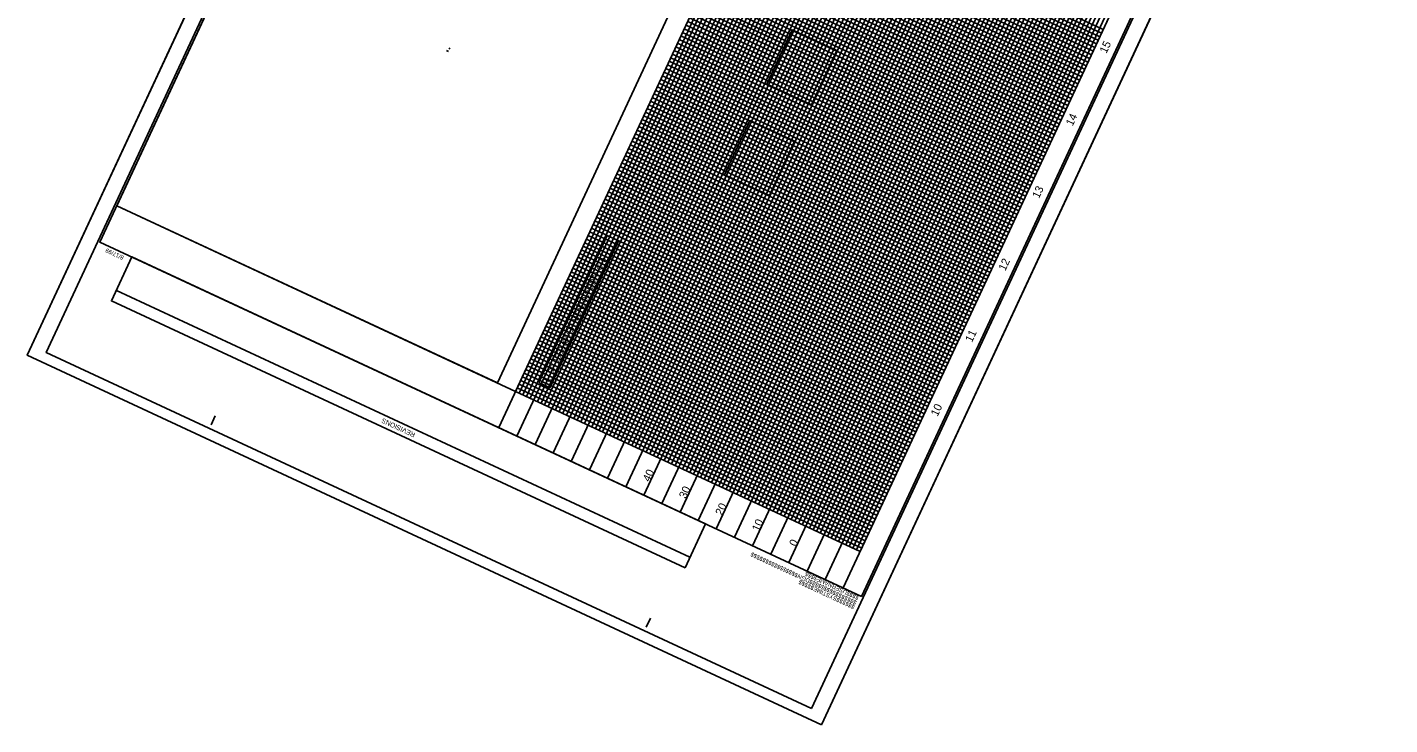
# Model space of a CAD drawing. Extents: x 2532214 to 2533961, y 714631 to 717266.
# Drawn here: x 2532214 to 2533917, y 714631 to 715503 of the extents above; entities that cross this region are included whole.
import ezdxf

# ---------------------------------------------------------------- set-up
doc = ezdxf.new("R2010")
doc.units = 0
for name, color, linetype in [('Default', 7, 'Continuous'), ('Exist Vertical Profile Horizontal Axis Label Major', 7, 'Continuous'), ('Exist Vertical Profile Vertical Axis Label', 7, 'Continuous'), ('Prop VPI Label', 7, 'Continuous'), ('Raster_Level_0', 7, 'Continuous'), ('Scratch_Level_0', 7, 'Continuous'), ('Scratch_Level_3', 7, 'Continuous'), ('Sheet Block Revision CELL', 7, 'Continuous'), ('Sheet Block System Information CELL', 7, 'Continuous'), ('Sheet Cutting Line CELL', 7, 'Continuous'), ('Sheet DOT Grid CELL', 7, 'Continuous'), ('Sheet Layout Plan Border', 7, 'Continuous'), ('Sheet Plan And Profile CELL', 7, 'Continuous'), ('Sheet Plot Border Inside CELL', 7, 'Continuous'), ('Sheet Plot Border Outside CELL', 7, 'Continuous'), ('Sheet Profile Grid Major CELL', 7, 'Continuous'), ('Sheet Profile Grid Middle CELL', 7, 'Continuous'), ('Sheet Profile Grid Minor CELL', 7, 'Continuous')]:
    doc.layers.add(name, color=color, linetype=linetype)

msp = doc.modelspace()

# ---------------------------------------------------------------- linework, layer by layer
at = {"layer": 'Default'}
for points in [[(2533138.5, 715432.1), (2533170.1, 715500.1), (2533226.1, 715474), (2533194.4, 715406)], [(2533138.5, 715432.1), (2533170.1, 715500.1), (2533226.1, 715474), (2533194.4, 715406)], [(2533085.7, 715318.7), (2533117.4, 715386.7), (2533173.3, 715360.7), (2533141.7, 715292.7)], [(2533085.7, 715318.7), (2533117.4, 715386.7), (2533173.3, 715360.7), (2533141.7, 715292.7)], [(2532853.4, 715059), (2532939, 715242.9), (2532953.1, 715236.4), (2532867.5, 715052.5)], [(2532853.4, 715059), (2532939, 715242.9), (2532953.1, 715236.4), (2532867.5, 715052.5)]]:
    msp.add_lwpolyline(points, close=True, dxfattribs=at)
at = {"layer": 'Raster_Level_0'}
for p, q in [((2532738.3, 715474.1), (2532740.7, 715473)), ((2532741, 715477.2), (2532742.8, 715476.4))]:
    msp.add_line(p, q, dxfattribs=at)
at = {"layer": 'Scratch_Level_0'}
msp.add_lwpolyline([(2532325.9, 715280), (2532853.1, 716413.3), (2533042.4, 716325.3), (2533126.8, 716506.7), (2533345.5, 716404.9), (2533436.2, 716362.7), (2533229.5, 715918.4), (2532824.5, 715048)], close=True, dxfattribs=at)
at = {"layer": 'Scratch_Level_3'}
msp.add_lwpolyline([(2532824.5, 715048), (2533229.5, 715918.4), (2533415.1, 716317.4), (2533539.1, 716259.7), (2533845.8, 716117), (2533255.2, 714847.7)], close=True, dxfattribs=at)
at = {"layer": 'Sheet Block Revision CELL'}
msp.add_line((2533042.4, 714840.8), (2532325.6, 715174.3), dxfattribs=at)
msp.add_lwpolyline([(2533036.3, 714827.6), (2532319.4, 715161.1), (2532345, 715216), (2533061.8, 714882.5)], close=True, dxfattribs=at)
at = {"layer": 'Sheet Block System Information CELL'}
msp.add_line((2533256.8, 714791.8), (2533256.8, 714791.8), dxfattribs=at)
at = {"layer": 'Sheet Cutting Line CELL'}
for p, q in [((2532924.3, 716619.6), (2532214.1, 715093.2)), ((2533206.9, 714631.3), (2533917.1, 716157.7)), ((2532214.1, 715093.2), (2533206.9, 714631.3))]:
    msp.add_line(p, q, dxfattribs=at)
at = {"layer": 'Sheet DOT Grid CELL'}
for p, q in [((2532939.4, 714939.4), (2533572.2, 716299.4)), ((2532848.8, 714981.6), (2533460.4, 716296.3)), ((2532894.1, 714960.5), (2533505.8, 716275.2)), ((2532984.8, 714918.3), (2533617.5, 716278.3)), ((2533030.1, 714897.2), (2533662.9, 716257.2)), ((2533075.4, 714876.1), (2533708.2, 716236.2)), ((2533120.8, 714855), (2533753.5, 716215.1)), ((2533166.1, 714834), (2533798.9, 716194)), ((2533211.4, 714812.9), (2533844.2, 716172.9)), ((2533119.8, 715682.7), (2533550.5, 715482.3)), ((2533098.7, 715637.4), (2533529.4, 715437)), ((2533077.6, 715592), (2533508.3, 715391.7)), ((2533056.5, 715546.7), (2533487.2, 715346.3)), ((2533035.4, 715501.4), (2533466.1, 715301)), ((2533014.4, 715456), (2533445, 715255.7)), ((2532993.3, 715410.7), (2533423.9, 715210.3)), ((2532972.2, 715365.4), (2533402.8, 715165)), ((2532951.1, 715320), (2533381.8, 715119.7)), ((2532930, 715274.7), (2533360.7, 715074.3)), ((2532908.9, 715229.4), (2533339.6, 715029)), ((2532887.8, 715184), (2533318.5, 714983.7)), ((2532866.7, 715138.7), (2533297.4, 714938.3)), ((2532845.6, 715093.4), (2533276.3, 714893))]:
    msp.add_line(p, q, dxfattribs=at)
at = {"layer": 'Sheet Layout Plan Border'}
msp.add_lwpolyline([(2532801.9, 715058.6), (2532325.9, 715280), (2532853.1, 716413.3), (2533042.4, 716325.3), (2533105.7, 716461.3), (2533392.4, 716327.9)], close=True, dxfattribs=at)
at = {"layer": 'Sheet Plan And Profile CELL'}
for p, q in [((2533436.2, 716362.7), (2532803.4, 715002.7)), ((2533866.9, 716162.3), (2533234.1, 714802.3)), ((2532443.9, 715006.2), (2532449.1, 715017.5)), ((2533256.8, 714791.8), (2533256.8, 714791.8)), ((2533256.8, 714791.8), (2533256.8, 714791.8)), ((2533256.8, 714791.8), (2533256.8, 714791.8)), ((2533256.8, 714791.8), (2533256.8, 714791.8)), ((2533256.8, 714791.8), (2533256.8, 714791.8)), ((2532987.9, 714753.1), (2532993.1, 714764.4))]:
    msp.add_line(p, q, dxfattribs=at)
msp.add_lwpolyline([(2532937.5, 716594.7), (2532304.8, 715234.7), (2533256.8, 714791.8), (2533889.5, 716151.8)], close=True, dxfattribs=at)
at = {"layer": 'Sheet Plot Border Inside CELL'}
msp.add_lwpolyline([(2533194.3, 714651.5), (2533897.1, 716162.1), (2532940.5, 716607.1), (2532237.8, 715096.6)], close=True, dxfattribs=at)
at = {"layer": 'Sheet Plot Border Outside CELL'}
msp.add_lwpolyline([(2533206.9, 714631.3), (2533917.1, 716157.7), (2532924.3, 716619.6), (2532214.1, 715093.2)], close=True, dxfattribs=at)
at = {"layer": 'Sheet Profile Grid Major CELL'}
for p, q in [((2533481.5, 716341.6), (2532848.8, 714981.6)), ((2532894.1, 714960.5), (2533526.9, 716320.5)), ((2533572.2, 716299.4), (2532939.4, 714939.4)), ((2532984.8, 714918.3), (2533617.5, 716278.3)), ((2533662.9, 716257.2), (2533030.1, 714897.2)), ((2533075.4, 714876.1), (2533708.2, 716236.2)), ((2533753.5, 716215.1), (2533120.8, 714855)), ((2533166.1, 714834), (2533798.9, 716194)), ((2533844.2, 716172.9), (2533211.4, 714812.9)), ((2533550.5, 715482.3), (2533119.8, 715682.7)), ((2533098.7, 715637.4), (2533529.4, 715437)), ((2533508.3, 715391.7), (2533077.6, 715592)), ((2533056.5, 715546.7), (2533487.2, 715346.3)), ((2533466.1, 715301), (2533035.4, 715501.4)), ((2533014.4, 715456), (2533445, 715255.7)), ((2533423.9, 715210.3), (2532993.3, 715410.7)), ((2532972.2, 715365.4), (2533402.8, 715165)), ((2533381.8, 715119.7), (2532951.1, 715320)), ((2532930, 715274.7), (2533360.7, 715074.3)), ((2533339.6, 715029), (2532908.9, 715229.4)), ((2532887.8, 715184), (2533318.5, 714983.7)), ((2533297.4, 714938.3), (2532866.7, 715138.7)), ((2532845.6, 715093.4), (2533276.3, 714893)), ((2533255.2, 714847.7), (2532824.5, 715048))]:
    msp.add_line(p, q, dxfattribs=at)
at = {"layer": 'Sheet Profile Grid Middle CELL'}
for p, q in [((2532826.1, 714992.1), (2533458.9, 716352.2)), ((2533504.2, 716331.1), (2532871.4, 714971.1)), ((2532916.8, 714950), (2533549.5, 716310)), ((2533594.9, 716288.9), (2532962.1, 714928.9)), ((2533007.4, 714907.8), (2533640.2, 716267.8)), ((2533685.5, 716246.7), (2533052.8, 714886.7)), ((2533098.1, 714865.6), (2533730.9, 716225.6)), ((2533776.2, 716204.5), (2533143.4, 714844.5)), ((2533188.8, 714823.4), (2533821.5, 716183.4)), ((2533109.3, 715660), (2533539.9, 715459.7)), ((2533518.8, 715414.3), (2533088.2, 715614.7)), ((2533067.1, 715569.4), (2533497.8, 715369)), ((2533476.7, 715323.7), (2533046, 715524)), ((2533024.9, 715478.7), (2533455.6, 715278.3)), ((2533434.5, 715233), (2533003.8, 715433.4)), ((2532982.7, 715388), (2533413.4, 715187.7)), ((2533392.3, 715142.3), (2532961.6, 715342.7)), ((2532940.5, 715297.4), (2533371.2, 715097)), ((2533350.1, 715051.7), (2532919.4, 715252)), ((2532898.4, 715206.7), (2533329, 715006.3)), ((2533307.9, 714961), (2532877.3, 715161.4)), ((2532856.2, 715116), (2533286.8, 714915.7)), ((2533265.8, 714870.3), (2532835.1, 715070.7))]:
    msp.add_line(p, q, dxfattribs=at)
at = {"layer": 'Sheet Profile Grid Minor CELL'}
for p, q in [((2533419.6, 716315.3), (2532829.1, 715045.9)), ((2532833.6, 715043.8), (2533424.2, 716313.2)), ((2533428.7, 716311), (2532838.1, 715041.7)), ((2532842.7, 715039.6), (2533433.2, 716308.9)), ((2533442.3, 716304.7), (2532851.7, 715035.4)), ((2532856.3, 715033.3), (2533446.8, 716302.6)), ((2533451.4, 716300.5), (2532860.8, 715031.1)), ((2532865.3, 715029), (2533455.9, 716298.4)), ((2533465, 716294.2), (2532874.4, 715024.8)), ((2532878.9, 715022.7), (2533469.5, 716292.1)), ((2533474, 716289.9), (2532883.5, 715020.6)), ((2532888, 715018.5), (2533478.6, 716287.8)), ((2533487.6, 716283.6), (2532897.1, 715014.3)), ((2532901.6, 715012.2), (2533492.2, 716281.5)), ((2533496.7, 716279.4), (2532906.1, 715010.1)), ((2532910.7, 715007.9), (2533501.2, 716277.3)), ((2532919.7, 715003.7), (2533510.3, 716273.1)), ((2533514.8, 716271), (2532924.3, 715001.6)), ((2532928.8, 714999.5), (2533519.4, 716268.9)), ((2533523.9, 716266.7), (2532933.3, 714997.4)), ((2532942.4, 714993.2), (2533533, 716262.5)), ((2533537.5, 716260.4), (2532946.9, 714991.1)), ((2532951.5, 714989), (2533542, 716258.3)), ((2533546.6, 716256.2), (2532956, 714986.9)), ((2532965.1, 714982.6), (2533555.6, 716252)), ((2533560.2, 716249.9), (2532969.6, 714980.5)), ((2532974.1, 714978.4), (2533564.7, 716247.8)), ((2533569.2, 716245.7), (2532978.7, 714976.3)), ((2532987.7, 714972.1), (2533578.3, 716241.4)), ((2533582.8, 716239.3), (2532992.3, 714970)), ((2532996.8, 714967.9), (2533587.4, 716237.2)), ((2533591.9, 716235.1), (2533001.3, 714965.8)), ((2533010.4, 714961.5), (2533601, 716230.9)), ((2533605.5, 716228.8), (2533014.9, 714959.4)), ((2533019.5, 714957.3), (2533610, 716226.7)), ((2533614.6, 716224.6), (2533024, 714955.2)), ((2533033.1, 714951), (2533623.6, 716220.3)), ((2533628.2, 716218.2), (2533037.6, 714948.9)), ((2533042.1, 714946.8), (2533632.7, 716216.1)), ((2533637.2, 716214), (2533046.7, 714944.7)), ((2533055.7, 714940.5), (2533646.3, 716209.8)), ((2533650.8, 716207.7), (2533060.3, 714938.3)), ((2533064.8, 714936.2), (2533655.4, 716205.6)), ((2533659.9, 716203.5), (2533069.3, 714934.1)), ((2533078.4, 714929.9), (2533669, 716199.3)), ((2533673.5, 716197.1), (2533082.9, 714927.8)), ((2533087.5, 714925.7), (2533678, 716195)), ((2533682.6, 716192.9), (2533092, 714923.6)), ((2533101.1, 714919.4), (2533691.6, 716188.7)), ((2533696.2, 716186.6), (2533105.6, 714917.3)), ((2533110.1, 714915.1), (2533700.7, 716184.5)), ((2533705.2, 716182.4), (2533114.7, 714913)), ((2533123.7, 714908.8), (2533714.3, 716178.2)), ((2533718.8, 716176.1), (2533128.3, 714906.7)), ((2533132.8, 714904.6), (2533723.4, 716173.9)), ((2533727.9, 716171.8), (2533137.3, 714902.5)), ((2533146.4, 714898.3), (2533737, 716167.6)), ((2533741.5, 716165.5), (2533150.9, 714896.2)), ((2533155.5, 714894.1), (2533746, 716163.4)), ((2533750.6, 716161.3), (2533160, 714891.9)), ((2533169.1, 714887.7), (2533759.6, 716157.1)), ((2533764.2, 716155), (2533173.6, 714885.6)), ((2533178.1, 714883.5), (2533768.7, 716152.9)), ((2533773.2, 716150.7), (2533182.7, 714881.4)), ((2533191.7, 714877.2), (2533782.3, 716146.5)), ((2533196.3, 714875.1), (2533786.8, 716144.4)), ((2533791.4, 716142.3), (2533200.8, 714873)), ((2533205.3, 714870.9), (2533795.9, 716140.2)), ((2533805, 716136), (2533214.4, 714866.6)), ((2533218.9, 714864.5), (2533809.5, 716133.9)), ((2533814, 716131.8), (2533223.5, 714862.4)), ((2533228, 714860.3), (2533818.6, 716129.7)), ((2533827.6, 716125.4), (2533237.1, 714856.1)), ((2533241.6, 714854), (2533832.2, 716123.3)), ((2533836.7, 716121.2), (2533246.1, 714851.9)), ((2533250.7, 714849.8), (2533841.2, 716119.1)), ((2533552.6, 715486.9), (2533121.9, 715687.2)), ((2533124, 715691.8), (2533554.7, 715491.4)), ((2533556.8, 715495.9), (2533126.1, 715696.3)), ((2533128.2, 715700.8), (2533558.9, 715500.5)), ((2533113.5, 715669.1), (2533544.2, 715468.7)), ((2533546.3, 715473.3), (2533115.6, 715673.6)), ((2533117.7, 715678.2), (2533548.4, 715477.8)), ((2533535.7, 715450.6), (2533105, 715651)), ((2533107.2, 715655.5), (2533537.8, 715455.1)), ((2533542, 715464.2), (2533111.4, 715664.6)), ((2533531.5, 715441.5), (2533100.8, 715641.9)), ((2533102.9, 715646.4), (2533533.6, 715446.1)), ((2533521, 715418.9), (2533090.3, 715619.2)), ((2533092.4, 715623.8), (2533523.1, 715423.4)), ((2533525.2, 715427.9), (2533094.5, 715628.3)), ((2533096.6, 715632.8), (2533527.3, 715432.5)), ((2533081.8, 715601.1), (2533512.5, 715400.7)), ((2533514.6, 715405.3), (2533084, 715605.6)), ((2533086.1, 715610.2), (2533516.7, 715409.8)), ((2533504.1, 715382.6), (2533073.4, 715583)), ((2533075.5, 715587.5), (2533506.2, 715387.1)), ((2533510.4, 715396.2), (2533079.7, 715596.6)), ((2533499.9, 715373.5), (2533069.2, 715573.9)), ((2533071.3, 715578.4), (2533502, 715378.1)), ((2533489.3, 715350.9), (2533058.6, 715551.2)), ((2533060.8, 715555.8), (2533491.4, 715355.4)), ((2533493.5, 715359.9), (2533062.9, 715560.3)), ((2533065, 715564.8), (2533495.6, 715364.5)), ((2533050.2, 715533.1), (2533480.9, 715332.7)), ((2533483, 715337.3), (2533052.3, 715537.6)), ((2533054.4, 715542.2), (2533485.1, 715341.8)), ((2533472.4, 715314.6), (2533041.8, 715515)), ((2533043.9, 715519.5), (2533474.6, 715319.1)), ((2533478.8, 715328.2), (2533048.1, 715528.6)), ((2533468.2, 715305.5), (2533037.6, 715505.9)), ((2533039.7, 715510.4), (2533470.3, 715310.1)), ((2533457.7, 715282.9), (2533027, 715483.2)), ((2533029.1, 715487.8), (2533459.8, 715287.4)), ((2533461.9, 715291.9), (2533031.2, 715492.3)), ((2533033.3, 715496.8), (2533464, 715296.5)), ((2533018.6, 715465.1), (2533449.2, 715264.7)), ((2533451.4, 715269.3), (2533020.7, 715469.6)), ((2533022.8, 715474.2), (2533453.5, 715273.8)), ((2533440.8, 715246.6), (2533010.1, 715447)), ((2533012.2, 715451.5), (2533442.9, 715251.1)), ((2533447.1, 715260.2), (2533016.5, 715460.6)), ((2533436.6, 715237.5), (2533005.9, 715437.9)), ((2533008, 715442.4), (2533438.7, 715242.1)), ((2533426, 715214.9), (2532995.4, 715415.2)), ((2532997.5, 715419.8), (2533428.2, 715219.4)), ((2533430.3, 715223.9), (2532999.6, 715424.3)), ((2533001.7, 715428.8), (2533432.4, 715228.5)), ((2532986.9, 715397.1), (2533417.6, 715196.7)), ((2533419.7, 715201.3), (2532989, 715401.6)), ((2532991.2, 715406.2), (2533421.8, 715205.8)), ((2533409.2, 715178.6), (2532978.5, 715379)), ((2532980.6, 715383.5), (2533411.3, 715183.1)), ((2533415.5, 715192.2), (2532984.8, 715392.6)), ((2533405, 715169.5), (2532974.3, 715369.9)), ((2532976.4, 715374.4), (2533407.1, 715174.1)), ((2533394.4, 715146.9), (2532963.7, 715347.2)), ((2532965.8, 715351.8), (2533396.5, 715151.4)), ((2533398.6, 715155.9), (2532968, 715356.3)), ((2532970.1, 715360.8), (2533400.7, 715160.5)), ((2532955.3, 715329.1), (2533386, 715128.7)), ((2533388.1, 715133.3), (2532957.4, 715333.6)), ((2532959.5, 715338.2), (2533390.2, 715137.8)), ((2533377.5, 715110.6), (2532946.9, 715311)), ((2532949, 715315.5), (2533379.6, 715115.1)), ((2533383.9, 715124.2), (2532953.2, 715324.6)), ((2533373.3, 715101.5), (2532942.6, 715301.9)), ((2532944.8, 715306.4), (2533375.4, 715106.1)), ((2533362.8, 715078.9), (2532932.1, 715279.2)), ((2532934.2, 715283.8), (2533364.9, 715083.4)), ((2533367, 715087.9), (2532936.3, 715288.3)), ((2532938.4, 715292.8), (2533369.1, 715092.5)), ((2532923.7, 715261.1), (2533354.3, 715060.7)), ((2533356.4, 715065.3), (2532925.8, 715265.6)), ((2532927.9, 715270.2), (2533358.6, 715069.8)), ((2533345.9, 715042.6), (2532915.2, 715243)), ((2532917.3, 715247.5), (2533348, 715047.1)), ((2533352.2, 715056.2), (2532921.6, 715256.6)), ((2532906.8, 715224.8), (2533337.5, 715024.5)), ((2533341.7, 715033.5), (2532911, 715233.9)), ((2532913.1, 715238.4), (2533343.8, 715038.1)), ((2533331.1, 715010.9), (2532900.5, 715211.2)), ((2532902.6, 715215.8), (2533333.2, 715015.4)), ((2533335.4, 715019.9), (2532904.7, 715220.3)), ((2532892, 715193.1), (2533322.7, 714992.7)), ((2533324.8, 714997.3), (2532894.1, 715197.6)), ((2532896.2, 715202.2), (2533326.9, 715001.8)), ((2533314.3, 714974.6), (2532883.6, 715175)), ((2532885.7, 715179.5), (2533316.4, 714979.1)), ((2533320.6, 714988.2), (2532889.9, 715188.6)), ((2532875.2, 715156.8), (2533305.8, 714956.5)), ((2533310, 714965.5), (2532879.4, 715165.9)), ((2532881.5, 715170.4), (2533312.2, 714970.1)), ((2533299.5, 714942.9), (2532868.8, 715143.2)), ((2532870.9, 715147.8), (2533301.6, 714947.4)), ((2533303.7, 714951.9), (2532873, 715152.3)), ((2532860.4, 715125.1), (2533291.1, 714924.7)), ((2533293.2, 714929.3), (2532862.5, 715129.6)), ((2532864.6, 715134.2), (2533295.3, 714933.8)), ((2533282.6, 714906.6), (2532852, 715107)), ((2532854.1, 715111.5), (2533284.7, 714911.1)), ((2533289, 714920.2), (2532858.3, 715120.6)), ((2532843.5, 715088.8), (2533274.2, 714888.5)), ((2533278.4, 714897.5), (2532847.7, 715097.9)), ((2532849.8, 715102.4), (2533280.5, 714902.1)), ((2533267.9, 714874.9), (2532837.2, 715075.2)), ((2532839.3, 715079.8), (2533270, 714879.4)), ((2533272.1, 714883.9), (2532841.4, 715084.3)), ((2532828.8, 715057.1), (2533259.4, 714856.7)), ((2533261.5, 714861.3), (2532830.9, 715061.6)), ((2532833, 715066.2), (2533263.6, 714865.8)), ((2533257.3, 714852.2), (2532826.6, 715052.6))]:
    msp.add_line(p, q, dxfattribs=at)

# ---------------------------------------------------------------- texts
at = {"layer": 'Exist Vertical Profile Horizontal Axis Label Major'}
for s, p in [('15', (2533562.9, 715469.6)), ('14', (2533520.7, 715378.9)), ('13', (2533478.6, 715288.4)), ('12', (2533436.5, 715197.8)), ('11', (2533394.9, 715108.5)), ('10', (2533351.9, 715016))]:
    msp.add_text(s, height=10, rotation=65.05, dxfattribs=at).set_placement(p)
at = {"layer": 'Exist Vertical Profile Vertical Axis Label'}
for s, p in [('40', (2532991.9, 714934.2)), ('30', (2533037.2, 714913.1)), ('20', (2533082.6, 714892)), ('10', (2533128.4, 714872)), ('0', (2533174.9, 714853.4))]:
    msp.add_text(s, height=10, rotation=65.05, dxfattribs=at).set_placement(p)
at = {"layer": 'Prop VPI Label'}
msp.add_text('-L- SR 1552 (OVER MEADOW BRANCH)', height=7, rotation=65.05, dxfattribs=at).set_placement((2532865, 715056.1))
at = {"layer": 'Sheet Block Revision CELL'}
msp.add_text('REVISIONS', height=6, rotation=155.05, dxfattribs=at).set_placement((2532699.7, 714995.8))
at = {"layer": 'Sheet Block System Information CELL'}
for s, p in [('$$$$$$$$$$$$$$$$DGN$$$$$$$$$$$$$$$$', (2533251.4, 714785.8)), ('$$$$USERNAME$$$$', (2533254.2, 714791.8)), ('$$$$$$SYSTIME$$$$$', (2533248.9, 714780.3))]:
    msp.add_text(s, height=5.25, rotation=155.05, dxfattribs=at).set_placement(p)
at = {"layer": 'Sheet Plan And Profile CELL'}
msp.add_text('8/17/99', height=5.25, rotation=155.05, dxfattribs=at).set_placement((2532335.3, 715216.9))

doc.saveas('drawing.dxf')
